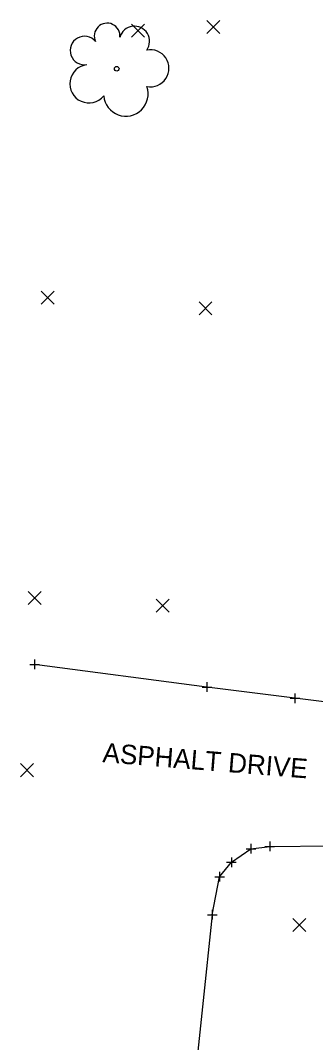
# Model space of a CAD drawing. Extents: x 1380550 to 1381945, y 468927 to 470496.
# Drawn here: x 1381468.1 to 1381498.4, y 469158.5 to 469263.7 of the extents above; entities that cross this region are included whole.
import ezdxf

# ---------------------------------------------------------------- set-up
doc = ezdxf.new("R2010")
doc.units = 0
for name, color, linetype in [('PV_X_Driveway', 7, 'Continuous'), ('RD_X_Text', 7, 'Continuous'), ('SV_X_Random_Point', 7, 'Continuous'), ('SV_X_Shot_Marker', 7, 'Continuous'), ('VG_X_Cells', 7, 'Continuous')]:
    doc.layers.add(name, color=color, linetype=linetype)

msp = doc.modelspace()

# ---------------------------------------------------------------- linework, layer by layer
at = {"layer": 'PV_X_Driveway'}
for points in [[(1381522.81, 469196), (1381520.24, 469194.81), (1381517.53, 469193.38), (1381515.86, 469192.8), (1381513.44, 469192.4), (1381511.17, 469192.5), (1381505.08, 469192.85), (1381496.32, 469193.94), (1381487.29, 469195.09), (1381469.58, 469197.42)], [(1381487.83, 469171.67), (1381488.59, 469175.57), (1381489.8, 469177.06), (1381491.8, 469178.46), (1381493.74, 469178.7), (1381500, 469178.74), (1381505.25, 469177.97), (1381510.63, 469175.94), (1381513.75, 469175.08), (1381519.99, 469168.46), (1381519.16, 469158.01), (1381519.54, 469157.13)], [(1381487.83, 469171.67), (1381485.85, 469152.72), (1381484.11, 469136.69)]]:
    msp.add_lwpolyline(points, dxfattribs=at)
at = {"layer": 'SV_X_Random_Point'}
for p, q in [((1381479.53, 469261.94), (1381480.86, 469263.28)), ((1381479.53, 469263.28), (1381480.86, 469261.94)), ((1381487.26, 469262.33), (1381488.6, 469263.67)), ((1381487.26, 469263.67), (1381488.6, 469262.33)), ((1381470.26, 469234.47), (1381471.59, 469235.81)), ((1381470.26, 469235.81), (1381471.59, 469234.47)), ((1381486.47, 469233.38), (1381487.8, 469234.71)), ((1381486.47, 469234.71), (1381487.8, 469233.38)), ((1381468.93, 469203.59), (1381470.26, 469204.93)), ((1381468.93, 469204.93), (1381470.26, 469203.59)), ((1381482.07, 469202.79), (1381483.4, 469204.12)), ((1381482.07, 469204.12), (1381483.4, 469202.79)), ((1381468.12, 469185.87), (1381469.46, 469187.21)), ((1381468.12, 469187.21), (1381469.46, 469185.87)), ((1381496.12, 469169.95), (1381497.46, 469171.29)), ((1381496.12, 469171.29), (1381497.46, 469169.95))]:
    msp.add_line(p, q, dxfattribs=at)
at = {"layer": 'SV_X_Shot_Marker'}
for p, q in [((1381469.58, 469197.92), (1381469.58, 469196.92)), ((1381469.08, 469197.42), (1381470.08, 469197.42)), ((1381469.58, 469197.42), (1381469.58, 469197.42)), ((1381487.29, 469195.59), (1381487.29, 469194.59)), ((1381486.79, 469195.09), (1381487.79, 469195.09)), ((1381487.29, 469195.09), (1381487.29, 469195.09)), ((1381496.32, 469194.44), (1381496.32, 469193.44)), ((1381495.82, 469193.94), (1381496.82, 469193.94)), ((1381496.32, 469193.94), (1381496.32, 469193.94)), ((1381491.8, 469178.96), (1381491.8, 469177.96)), ((1381493.24, 469178.7), (1381494.24, 469178.7)), ((1381493.74, 469179.2), (1381493.74, 469178.2)), ((1381493.74, 469178.7), (1381493.74, 469178.7)), ((1381489.8, 469177.56), (1381489.8, 469176.56)), ((1381491.3, 469178.46), (1381492.3, 469178.46)), ((1381491.8, 469178.46), (1381491.8, 469178.46)), ((1381489.3, 469177.06), (1381490.3, 469177.06)), ((1381489.8, 469177.06), (1381489.8, 469177.06)), ((1381488.09, 469175.57), (1381489.09, 469175.57)), ((1381488.59, 469176.07), (1381488.59, 469175.07)), ((1381488.59, 469175.57), (1381488.59, 469175.57)), ((1381487.33, 469171.67), (1381488.33, 469171.67)), ((1381487.33, 469171.67), (1381488.33, 469171.67)), ((1381487.83, 469172.17), (1381487.83, 469171.17)), ((1381487.83, 469172.17), (1381487.83, 469171.17)), ((1381487.83, 469171.67), (1381487.83, 469171.67)), ((1381487.83, 469171.67), (1381487.83, 469171.67))]:
    msp.add_line(p, q, dxfattribs=at)
at = {"layer": 'VG_X_Cells'}
msp.add_circle((1381478.01, 469258.7), 0.24, dxfattribs=at)
for centre, radius, start, end in [((1381477.03, 469262.07), 1.32, 354.0047, 205.9741), ((1381479.84, 469261.53), 1.55, 323.83, 165.0376), ((1381474.7, 469260.57), 1.47, 39.0625, 279.5412), ((1381481.47, 469258.74), 1.91, 259.1453, 101.4596), ((1381475.16, 469257.15), 1.97, 96.1722, 320.5737), ((1381478.96, 469256.1), 2.28, 184.9476, 19.4572)]:
    msp.add_arc(centre, radius, start, end, dxfattribs=at)

# ---------------------------------------------------------------- texts
at = {"layer": 'RD_X_Text'}
msp.add_text('ASPHALT DRIVE', height=2, rotation=355.4428, dxfattribs=at).set_placement((1381476.51, 469187.37))

doc.saveas('drawing.dxf')
